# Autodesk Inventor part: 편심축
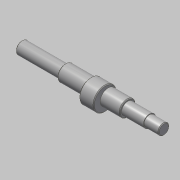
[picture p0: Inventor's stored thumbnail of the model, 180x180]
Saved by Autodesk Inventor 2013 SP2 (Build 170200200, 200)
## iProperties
Created: 2016-05
Part Number: 편심축
Document SubType Name: Modeling
Designer: mduedu
Density: 7.86 g/cm^3
Material: 강철, 연강
Author: mduedu
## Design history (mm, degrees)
sketch "스케치1"
  geometry: L1 (-38, 11)-(-38, 8.5); L2 (48, 11)-(48, 8.5); L3 (-98, 0)-(98, 0); L4 (-38, 11)-(48, 11); L5 (48, 11)-(48, 8.5); L6 (-38, 11)-(-38, 8.5); L7 (-38, 8.5)-(-98, 8.5); L8 (-98, 8.5)-(-98, 0); L9 (48, 8.5)-(78, 8.5); L10 (98, 7.5)-(98, 0); L11 (78, 8.5)-(78, 7.5); L12 (78, 7.5)-(98, 7.5); 1 further point
  constraints: 24 end point, 9 perpendicular, 2 midpoint, 1 collinear, 1 horizontal
  dimensions: "d0" = 22 diameter of L4 L3; "d1" = 17 diameter of L7 L3; "d2" = 60 distance between parallel lines of L8 L1; "d3" = 50 distance between parallel lines of L10 L2; "d4" = 15 diameter of L12 L3; "d5" = 20 distance between parallel lines of L10 L11; "d29" = 86 distance of L1.start L2.start
revolve "회전1" stored, may be unused: angle "d6" = 90 deg
node "작업 평면7"
node "작업 평면9"
sketch "스케치2"
  geometry: C1 r 11 at (0, 0); C2 r 16 at (0, -4); C3 r 11 at (0, 0); 2 further points
  constraints: 3 centre point, 2 coincident, 1 concentric, 1 vertical alignment
  dimensions: "d9" = 4 distance of point (0, 0) C2.centre; "d10" = 32 diameter of C2
extrude "돌출1" join sketch "스케치2" stored distance "d11" = 20; taper "d12" = 0 deg
chamfer "모따기1" distance "d17" = 1; stored, may be unused: second distance "d18" = 2, angle "d19" = 45 deg
node "작업 평면4"
sketch "스케치4"
  geometry: L1 (-10, -6.5)-(-10, 6.5) reference; L2 (-5, 2.5)-(5, 2.5); L3 (5, -2.5)-(-5, -2.5); A1 r 2.5 centre (5, 0) between (5, -2.5) and (5, 2.5); A2 r 2.5 centre (-5, 0) between (-5, 2.5) and (-5, -2.5); 2 further points
  constraints: 4 end point, 4 point on circle, 4 tangent, 2 centre point, 1 horizontal alignment, 1 midpoint, 1 parallel, 1 perpendicular
  dimensions: "d20" = 5 distance between parallel lines of L3 L2; "d21" = 15 dimension on A1 A2; "d22" = 2.5 distance edge to line of A2 L1
extrude "돌출3" cut sketch "스케치4" distance "d23" = 3; taper "d24" = 0 deg
node "작업 평면5"
sketch "스케치5"
  geometry: L1 (30, 7.5)-(30, -7.5) reference; L2 (30, 2.5)-(12.5, 2.5); L3 (12.5, -2.5)-(30, -2.5); A1 r 2.5 centre (12.5, 0) between (12.5, 2.5) and (12.5, -2.5); 2 further points
  constraints: 4 end point, 2 perpendicular, 2 point on circle, 2 point on line, 2 tangent, 1 centre point, 1 horizontal alignment, 1 midpoint
  dimensions: "d25" = 5 distance between parallel lines of L3 L2; "d26" = 20 dimension on A1 L1
extrude "돌출4" cut sketch "스케치5" distance "d27" = 3; taper "d28" = 0 deg
node "솔리드1"
other parameters: "d31" = -37
